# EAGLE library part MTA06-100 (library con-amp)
AMP connector
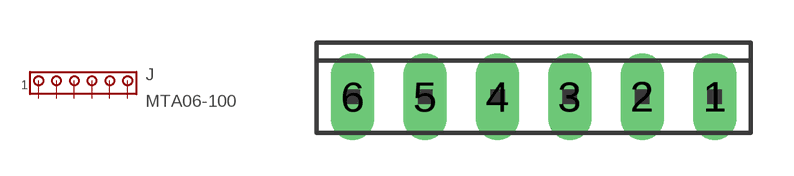
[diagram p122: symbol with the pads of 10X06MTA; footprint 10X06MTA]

Designator prefix J

## MTA06-100 (OC_FARNELL: unknown; OC_NEWARK: unknown)  [10X06MTA]
1  6  pas
2  5  pas
3  4  pas
4  3  pas
5  2  pas
6  1  pas

## Footprint 10X06MTA (pad centres in mm)
AMP MTA connector Source: http://ecommas.tycoelectronics.com .. ENG_CD_640456_W.pdf
drill 1.016 long: 1 6.35,0; 2 3.81,0; 3 1.27,0; 4 -1.27,0; 5 -3.81,0; 6 -6.35,0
